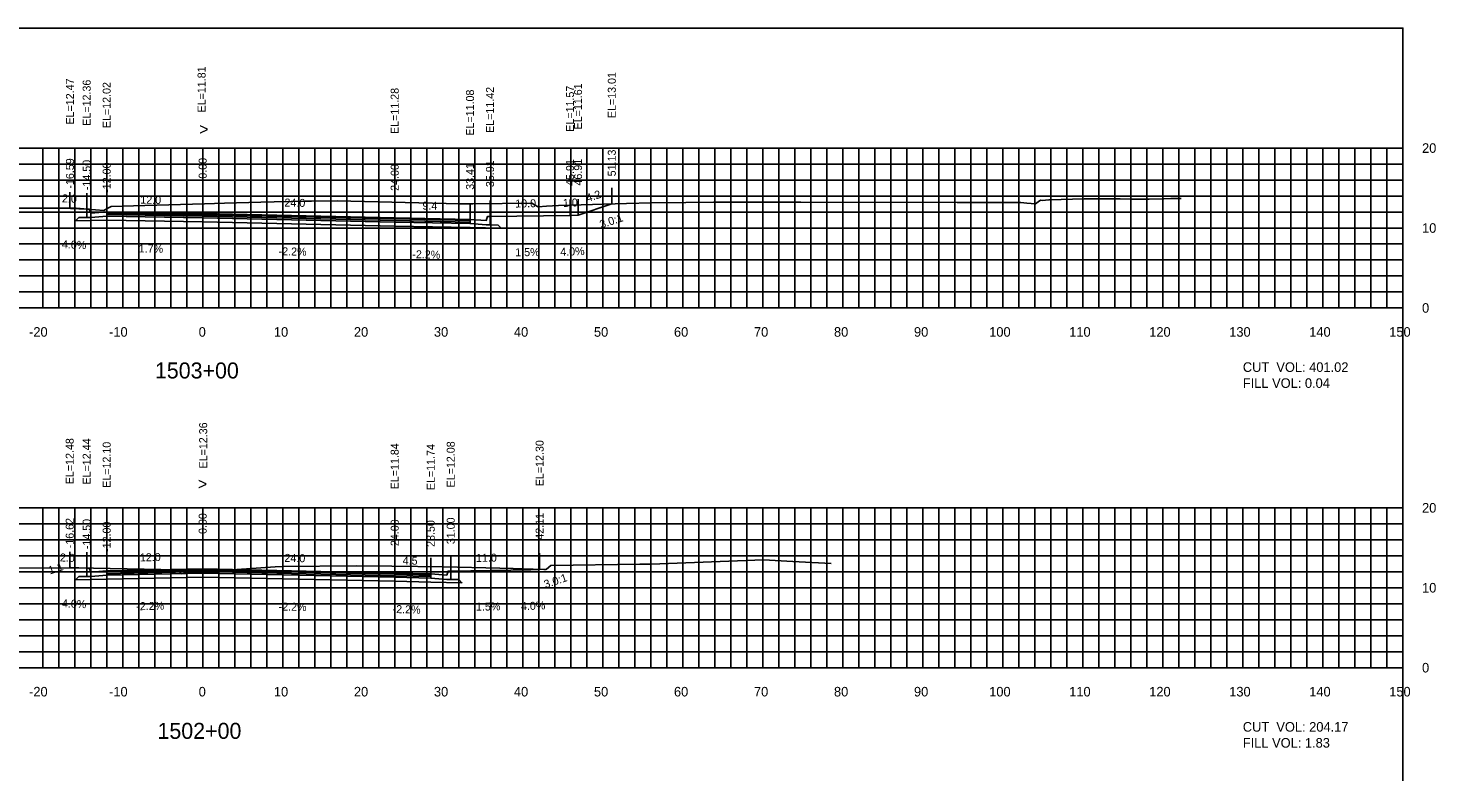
# Model space of a CAD drawing. Extents: x 1800674 to 1802785, y 250079 to 250269.
# Drawn here: x 1802269.2 to 1802445.1, y 250176.4 to 250269.4 of the extents above; entities that cross this region are included whole.
import ezdxf

# ---------------------------------------------------------------- set-up
doc = ezdxf.new("R2010")
doc.units = 0
for name, color, linetype in [('1', 7, 'Continuous'), ('10', 7, 'Continuous'), ('3', 7, 'Continuous'), ('31', 7, 'Continuous'), ('4', 7, 'Continuous'), ('60', 7, 'Continuous'), ('ANNO-TXT', 7, 'Continuous'), ('BASE', 7, 'Continuous'), ('CL-CNST', 7, 'Continuous'), ('Level 62', 7, 'Continuous'), ('LOWER BINDER', 7, 'Continuous'), ('M-ROADS', 7, 'Continuous'), ('UPPER BINDER', 7, 'Continuous'), ('WEARING', 7, 'Continuous')]:
    doc.layers.add(name, color=color, linetype=linetype)

msp = doc.modelspace()

# ---------------------------------------------------------------- linework, layer by layer
for p, q in [((1802342.13, 250247.44), (1802342.13, 250249.44)), ((1802274.41, 250246.9), (1802274.41, 250248.9)), ((1802276.5, 250246.79), (1802276.5, 250248.79)), ((1802279, 250246.45), (1802279, 250248.45)), ((1802291, 250246.24), (1802291, 250248.24)), ((1802315, 250245.71), (1802315, 250247.71)), ((1802324.41, 250245.51), (1802324.41, 250247.51)), ((1802326.91, 250245.85), (1802326.91, 250247.85)), ((1802336.91, 250246), (1802336.91, 250248)), ((1802337.91, 250246.04), (1802337.91, 250248.04)), ((1802274.38, 250201.91), (1802274.38, 250203.91)), ((1802276.5, 250201.87), (1802276.5, 250203.87)), ((1802279, 250201.53), (1802279, 250203.53)), ((1802291, 250201.8), (1802291, 250203.8)), ((1802322, 250201.51), (1802322, 250203.51)), ((1802333.11, 250201.74), (1802333.11, 250203.74)), ((1802315, 250201.27), (1802315, 250203.27)), ((1802319.5, 250201.17), (1802319.5, 250203.17))]:
    msp.add_line(p, q)
for points in [[(1802141, 250079.43), (1802441, 250079.43), (1802441, 250269.43), (1802141, 250269.43)], [(1802279, 250246.45), (1802277, 250246.29), (1802276.83, 250246.79), (1802276.5, 250246.79), (1802276.5, 250245.76), (1802277, 250245.76), (1802279, 250245.92)], [(1802324.41, 250245.51), (1802326.41, 250245.35), (1802326.58, 250245.85), (1802326.91, 250245.85), (1802326.91, 250244.82), (1802326.41, 250244.82), (1802324.41, 250244.98)], [(1802279, 250201.53), (1802277, 250201.37), (1802276.83, 250201.87), (1802276.5, 250201.87), (1802276.5, 250200.84), (1802277, 250200.84), (1802279, 250201)], [(1802319.5, 250201.17), (1802321.5, 250201.01), (1802321.67, 250201.51), (1802322, 250201.51), (1802322, 250200.48), (1802321.5, 250200.48), (1802319.5, 250200.64)]]:
    msp.add_lwpolyline(points, close=True)
msp.add_lwpolyline([(1802274.5, 250201.95), (1802274.38, 250201.91)])
at = {"layer": '60'}
for p, q in [((1802441, 250234.43), (1802441, 250254.43)), ((1802441.06, 250254.43), (1802441, 250254.43)), ((1802441.06, 250244.43), (1802441, 250244.43)), ((1802141, 250234.43), (1802441, 250234.43)), ((1802271, 250234.37), (1802271, 250234.43)), ((1802281, 250234.37), (1802281, 250234.43)), ((1802291, 250234.37), (1802291, 250234.43)), ((1802301, 250234.37), (1802301, 250234.43)), ((1802311, 250234.37), (1802311, 250234.43)), ((1802321, 250234.37), (1802321, 250234.43)), ((1802331, 250234.37), (1802331, 250234.43)), ((1802341, 250234.37), (1802341, 250234.43)), ((1802351, 250234.37), (1802351, 250234.43)), ((1802361, 250234.37), (1802361, 250234.43)), ((1802371, 250234.37), (1802371, 250234.43)), ((1802381, 250234.37), (1802381, 250234.43)), ((1802391, 250234.37), (1802391, 250234.43)), ((1802401, 250234.37), (1802401, 250234.43)), ((1802411, 250234.37), (1802411, 250234.43)), ((1802421, 250234.37), (1802421, 250234.43)), ((1802431, 250234.37), (1802431, 250234.43)), ((1802441, 250234.37), (1802441, 250234.43)), ((1802441.06, 250234.43), (1802441, 250234.43)), ((1802441, 250189.43), (1802441, 250209.43)), ((1802441.06, 250209.43), (1802441, 250209.43)), ((1802441.06, 250199.43), (1802441, 250199.43)), ((1802141, 250189.43), (1802441, 250189.43)), ((1802271, 250189.37), (1802271, 250189.43)), ((1802281, 250189.37), (1802281, 250189.43)), ((1802291, 250189.37), (1802291, 250189.43)), ((1802301, 250189.37), (1802301, 250189.43)), ((1802311, 250189.37), (1802311, 250189.43)), ((1802321, 250189.37), (1802321, 250189.43)), ((1802331, 250189.37), (1802331, 250189.43)), ((1802341, 250189.37), (1802341, 250189.43)), ((1802351, 250189.37), (1802351, 250189.43)), ((1802361, 250189.37), (1802361, 250189.43)), ((1802371, 250189.37), (1802371, 250189.43)), ((1802381, 250189.37), (1802381, 250189.43)), ((1802391, 250189.37), (1802391, 250189.43)), ((1802401, 250189.37), (1802401, 250189.43)), ((1802411, 250189.37), (1802411, 250189.43)), ((1802421, 250189.37), (1802421, 250189.43)), ((1802431, 250189.37), (1802431, 250189.43)), ((1802441, 250189.37), (1802441, 250189.43)), ((1802441.06, 250189.43), (1802441, 250189.43))]:
    msp.add_line(p, q, dxfattribs=at)
at = {"layer": 'BASE'}
for points in [[(1802324.41, 250244.48), (1802328.31, 250244.39), (1802327.91, 250244.8), (1802326.91, 250244.82), (1802326.41, 250244.82), (1802324.41, 250244.98), (1802315, 250245.18), (1802291, 250245.71), (1802279, 250245.92), (1802277, 250245.76), (1802276.5, 250245.76), (1802275.5, 250245.74), (1802275.1, 250245.34), (1802279, 250245.42), (1802291, 250245.21), (1802315, 250244.68)], [(1802319.5, 250200.14), (1802323.4, 250200.05), (1802323, 250200.46), (1802322, 250200.48), (1802321.5, 250200.48), (1802319.5, 250200.64), (1802315, 250200.74), (1802291, 250201.27), (1802279, 250201), (1802277, 250200.84), (1802276.5, 250200.84), (1802275.5, 250200.82), (1802275.1, 250200.42), (1802279, 250200.5), (1802291, 250200.77), (1802315, 250200.24)]]:
    msp.add_lwpolyline(points, close=True, dxfattribs=at)
at = {"layer": 'CL-CNST'}
for points in [[(1802274.41, 250246.9), (1802274.5, 250246.87), (1802276.5, 250246.79), (1802276.83, 250246.79), (1802277, 250246.29), (1802279, 250246.45), (1802291, 250246.24), (1802315, 250245.71), (1802324.41, 250245.51), (1802326.41, 250245.35), (1802326.58, 250245.85), (1802326.91, 250245.85), (1802336.91, 250246), (1802337.91, 250246.04), (1802342.13, 250247.44)], [(1802274.38, 250201.91), (1802274.5, 250201.95), (1802276.5, 250201.87), (1802276.83, 250201.87), (1802277, 250201.37), (1802279, 250201.53), (1802291, 250201.8), (1802315, 250201.27), (1802319.5, 250201.17), (1802321.5, 250201.01), (1802321.67, 250201.51), (1802322, 250201.51), (1802332, 250201.66), (1802333, 250201.7), (1802333.11, 250201.74)]]:
    msp.add_lwpolyline(points, dxfattribs=at)
at = {"layer": 'Level 62'}
for p, q in [((1802141, 250254.43), (1802441, 250254.43)), ((1802271, 250234.43), (1802271, 250254.43)), ((1802273, 250234.43), (1802273, 250254.43)), ((1802275, 250234.43), (1802275, 250254.43)), ((1802277, 250234.43), (1802277, 250254.43)), ((1802279, 250234.43), (1802279, 250254.43)), ((1802281, 250234.43), (1802281, 250254.43)), ((1802283, 250234.43), (1802283, 250254.43)), ((1802285, 250234.43), (1802285, 250254.43)), ((1802287, 250234.43), (1802287, 250254.43)), ((1802289, 250234.43), (1802289, 250254.43)), ((1802291, 250234.43), (1802291, 250254.43)), ((1802293, 250234.43), (1802293, 250254.43)), ((1802295, 250234.43), (1802295, 250254.43)), ((1802297, 250234.43), (1802297, 250254.43)), ((1802299, 250234.43), (1802299, 250254.43)), ((1802301, 250234.43), (1802301, 250254.43)), ((1802303, 250234.43), (1802303, 250254.43)), ((1802305, 250234.43), (1802305, 250254.43)), ((1802307, 250234.43), (1802307, 250254.43)), ((1802309, 250234.43), (1802309, 250254.43)), ((1802311, 250234.43), (1802311, 250254.43)), ((1802313, 250234.43), (1802313, 250254.43)), ((1802315, 250234.43), (1802315, 250254.43)), ((1802317, 250234.43), (1802317, 250254.43)), ((1802319, 250234.43), (1802319, 250254.43)), ((1802321, 250234.43), (1802321, 250254.43)), ((1802323, 250234.43), (1802323, 250254.43)), ((1802325, 250234.43), (1802325, 250254.43)), ((1802327, 250234.43), (1802327, 250254.43)), ((1802329, 250234.43), (1802329, 250254.43)), ((1802331, 250234.43), (1802331, 250254.43)), ((1802333, 250234.43), (1802333, 250254.43)), ((1802335, 250234.43), (1802335, 250254.43)), ((1802337, 250234.43), (1802337, 250254.43)), ((1802339, 250234.43), (1802339, 250254.43)), ((1802341, 250234.43), (1802341, 250254.43)), ((1802343, 250234.43), (1802343, 250254.43)), ((1802345, 250234.43), (1802345, 250254.43)), ((1802347, 250234.43), (1802347, 250254.43)), ((1802349, 250234.43), (1802349, 250254.43)), ((1802351, 250234.43), (1802351, 250254.43)), ((1802353, 250234.43), (1802353, 250254.43)), ((1802355, 250234.43), (1802355, 250254.43)), ((1802357, 250234.43), (1802357, 250254.43)), ((1802359, 250234.43), (1802359, 250254.43)), ((1802361, 250234.43), (1802361, 250254.43)), ((1802363, 250234.43), (1802363, 250254.43)), ((1802365, 250234.43), (1802365, 250254.43)), ((1802367, 250234.43), (1802367, 250254.43)), ((1802369, 250234.43), (1802369, 250254.43)), ((1802371, 250234.43), (1802371, 250254.43)), ((1802373, 250234.43), (1802373, 250254.43)), ((1802375, 250234.43), (1802375, 250254.43)), ((1802377, 250234.43), (1802377, 250254.43)), ((1802379, 250234.43), (1802379, 250254.43)), ((1802381, 250234.43), (1802381, 250254.43)), ((1802383, 250234.43), (1802383, 250254.43)), ((1802385, 250234.43), (1802385, 250254.43)), ((1802387, 250234.43), (1802387, 250254.43)), ((1802389, 250234.43), (1802389, 250254.43)), ((1802391, 250234.43), (1802391, 250254.43)), ((1802393, 250234.43), (1802393, 250254.43)), ((1802395, 250234.43), (1802395, 250254.43)), ((1802397, 250234.43), (1802397, 250254.43)), ((1802399, 250234.43), (1802399, 250254.43)), ((1802401, 250234.43), (1802401, 250254.43)), ((1802403, 250234.43), (1802403, 250254.43)), ((1802405, 250234.43), (1802405, 250254.43)), ((1802407, 250234.43), (1802407, 250254.43)), ((1802409, 250234.43), (1802409, 250254.43)), ((1802411, 250234.43), (1802411, 250254.43)), ((1802413, 250234.43), (1802413, 250254.43)), ((1802415, 250234.43), (1802415, 250254.43)), ((1802417, 250234.43), (1802417, 250254.43)), ((1802419, 250234.43), (1802419, 250254.43)), ((1802421, 250234.43), (1802421, 250254.43)), ((1802423, 250234.43), (1802423, 250254.43)), ((1802425, 250234.43), (1802425, 250254.43)), ((1802427, 250234.43), (1802427, 250254.43)), ((1802429, 250234.43), (1802429, 250254.43)), ((1802431, 250234.43), (1802431, 250254.43)), ((1802433, 250234.43), (1802433, 250254.43)), ((1802435, 250234.43), (1802435, 250254.43)), ((1802437, 250234.43), (1802437, 250254.43)), ((1802439, 250234.43), (1802439, 250254.43)), ((1802441, 250234.43), (1802441, 250254.43)), ((1802141, 250252.43), (1802441, 250252.43)), ((1802141, 250250.43), (1802441, 250250.43)), ((1802141, 250248.43), (1802441, 250248.43)), ((1802141, 250246.43), (1802441, 250246.43)), ((1802141, 250244.43), (1802441, 250244.43)), ((1802141, 250242.43), (1802441, 250242.43)), ((1802141, 250240.43), (1802441, 250240.43)), ((1802141, 250238.43), (1802441, 250238.43)), ((1802141, 250236.43), (1802441, 250236.43)), ((1802141, 250234.43), (1802441, 250234.43)), ((1802141, 250209.43), (1802441, 250209.43)), ((1802271, 250189.43), (1802271, 250209.43)), ((1802273, 250189.43), (1802273, 250209.43)), ((1802275, 250189.43), (1802275, 250209.43)), ((1802277, 250189.43), (1802277, 250209.43)), ((1802279, 250189.43), (1802279, 250209.43)), ((1802281, 250189.43), (1802281, 250209.43)), ((1802283, 250189.43), (1802283, 250209.43)), ((1802285, 250189.43), (1802285, 250209.43)), ((1802287, 250189.43), (1802287, 250209.43)), ((1802289, 250189.43), (1802289, 250209.43)), ((1802291, 250189.43), (1802291, 250209.43)), ((1802293, 250189.43), (1802293, 250209.43)), ((1802295, 250189.43), (1802295, 250209.43)), ((1802297, 250189.43), (1802297, 250209.43)), ((1802299, 250189.43), (1802299, 250209.43)), ((1802301, 250189.43), (1802301, 250209.43)), ((1802303, 250189.43), (1802303, 250209.43)), ((1802305, 250189.43), (1802305, 250209.43)), ((1802307, 250189.43), (1802307, 250209.43)), ((1802309, 250189.43), (1802309, 250209.43)), ((1802311, 250189.43), (1802311, 250209.43)), ((1802313, 250189.43), (1802313, 250209.43)), ((1802315, 250189.43), (1802315, 250209.43)), ((1802317, 250189.43), (1802317, 250209.43)), ((1802319, 250189.43), (1802319, 250209.43)), ((1802321, 250189.43), (1802321, 250209.43)), ((1802323, 250189.43), (1802323, 250209.43)), ((1802325, 250189.43), (1802325, 250209.43)), ((1802327, 250189.43), (1802327, 250209.43)), ((1802329, 250189.43), (1802329, 250209.43)), ((1802331, 250189.43), (1802331, 250209.43)), ((1802333, 250189.43), (1802333, 250209.43)), ((1802335, 250189.43), (1802335, 250209.43)), ((1802337, 250189.43), (1802337, 250209.43)), ((1802339, 250189.43), (1802339, 250209.43)), ((1802341, 250189.43), (1802341, 250209.43)), ((1802343, 250189.43), (1802343, 250209.43)), ((1802345, 250189.43), (1802345, 250209.43)), ((1802347, 250189.43), (1802347, 250209.43)), ((1802349, 250189.43), (1802349, 250209.43)), ((1802351, 250189.43), (1802351, 250209.43)), ((1802353, 250189.43), (1802353, 250209.43)), ((1802355, 250189.43), (1802355, 250209.43)), ((1802357, 250189.43), (1802357, 250209.43)), ((1802359, 250189.43), (1802359, 250209.43)), ((1802361, 250189.43), (1802361, 250209.43)), ((1802363, 250189.43), (1802363, 250209.43)), ((1802365, 250189.43), (1802365, 250209.43)), ((1802367, 250189.43), (1802367, 250209.43)), ((1802369, 250189.43), (1802369, 250209.43)), ((1802371, 250189.43), (1802371, 250209.43)), ((1802373, 250189.43), (1802373, 250209.43)), ((1802375, 250189.43), (1802375, 250209.43)), ((1802377, 250189.43), (1802377, 250209.43)), ((1802379, 250189.43), (1802379, 250209.43)), ((1802381, 250189.43), (1802381, 250209.43)), ((1802383, 250189.43), (1802383, 250209.43)), ((1802385, 250189.43), (1802385, 250209.43)), ((1802387, 250189.43), (1802387, 250209.43)), ((1802389, 250189.43), (1802389, 250209.43)), ((1802391, 250189.43), (1802391, 250209.43)), ((1802393, 250189.43), (1802393, 250209.43)), ((1802395, 250189.43), (1802395, 250209.43)), ((1802397, 250189.43), (1802397, 250209.43)), ((1802399, 250189.43), (1802399, 250209.43)), ((1802401, 250189.43), (1802401, 250209.43)), ((1802403, 250189.43), (1802403, 250209.43)), ((1802405, 250189.43), (1802405, 250209.43)), ((1802407, 250189.43), (1802407, 250209.43)), ((1802409, 250189.43), (1802409, 250209.43)), ((1802411, 250189.43), (1802411, 250209.43)), ((1802413, 250189.43), (1802413, 250209.43)), ((1802415, 250189.43), (1802415, 250209.43)), ((1802417, 250189.43), (1802417, 250209.43)), ((1802419, 250189.43), (1802419, 250209.43)), ((1802421, 250189.43), (1802421, 250209.43)), ((1802423, 250189.43), (1802423, 250209.43)), ((1802425, 250189.43), (1802425, 250209.43)), ((1802427, 250189.43), (1802427, 250209.43)), ((1802429, 250189.43), (1802429, 250209.43)), ((1802431, 250189.43), (1802431, 250209.43)), ((1802433, 250189.43), (1802433, 250209.43)), ((1802435, 250189.43), (1802435, 250209.43)), ((1802437, 250189.43), (1802437, 250209.43)), ((1802439, 250189.43), (1802439, 250209.43)), ((1802441, 250189.43), (1802441, 250209.43)), ((1802141, 250207.43), (1802441, 250207.43)), ((1802141, 250205.43), (1802441, 250205.43)), ((1802141, 250203.43), (1802441, 250203.43)), ((1802141, 250201.43), (1802441, 250201.43)), ((1802141, 250199.43), (1802441, 250199.43)), ((1802141, 250197.43), (1802441, 250197.43)), ((1802141, 250195.43), (1802441, 250195.43)), ((1802141, 250193.43), (1802441, 250193.43)), ((1802141, 250191.43), (1802441, 250191.43)), ((1802141, 250189.43), (1802441, 250189.43))]:
    msp.add_line(p, q, dxfattribs=at)
at = {"layer": 'LOWER BINDER'}
for points in [[(1802279, 250245.92), (1802279, 250246.11), (1802291, 250245.9), (1802315, 250245.37), (1802324.41, 250245.17), (1802324.41, 250244.98), (1802315, 250245.18), (1802291, 250245.71)], [(1802279, 250201), (1802279, 250201.19), (1802291, 250201.46), (1802315, 250200.93), (1802319.5, 250200.83), (1802319.5, 250200.64), (1802315, 250200.74), (1802291, 250201.27)]]:
    msp.add_lwpolyline(points, close=True, dxfattribs=at)
at = {"layer": 'M-ROADS'}
for points in [[(1802265.15, 250246.92), (1802270.89, 250246.9), (1802275.2, 250246.9), (1802275.7, 250246.86), (1802277.59, 250246.71), (1802278.65, 250246.63), (1802279.15, 250246.91), (1802279.56, 250247.12), (1802283.78, 250247.24), (1802291.21, 250247.45), (1802293.73, 250247.52), (1802298.26, 250247.65), (1802299.94, 250247.69), (1802302.04, 250247.74), (1802303.81, 250247.77), (1802304.61, 250247.78), (1802307.8, 250247.81), (1802323.13, 250247.46), (1802324.78, 250247.46), (1802332.13, 250247.55), (1802332.49, 250247.33), (1802332.91, 250247.09), (1802333.96, 250247.15), (1802335.48, 250247.26), (1802343.96, 250247.49), (1802347.09, 250247.57), (1802351.37, 250247.62), (1802354.83, 250247.65), (1802361.94, 250247.66), (1802365.76, 250247.66), (1802385.29, 250247.62), (1802393.24, 250247.63), (1802394.02, 250247.55), (1802395.1, 250247.45), (1802395.41, 250247.71), (1802395.7, 250247.93), (1802395.93, 250247.88), (1802396.77, 250247.97), (1802396.8, 250247.97), (1802396.83, 250247.97), (1802401.19, 250248.07), (1802403.57, 250248.07), (1802405.68, 250248.06), (1802406.96, 250248.05), (1802407.77, 250248.04), (1802409.3, 250248.05), (1802411.13, 250248.09), (1802412.01, 250248.11), (1802413.28, 250248.12)], [(1802255.78, 250201.86), (1802275.21, 250201.91), (1802287.88, 250201.69), (1802287.98, 250201.58), (1802288.32, 250201.19), (1802289.53, 250201.33), (1802289.97, 250201.36), (1802293.47, 250201.59), (1802300.04, 250202.06), (1802300.96, 250202.07), (1802310.27, 250202.19), (1802314.66, 250202.14), (1802321.1, 250202.06), (1802328.14, 250201.88), (1802329.82, 250201.83), (1802332.29, 250201.77), (1802333.64, 250201.71), (1802333.9, 250201.7), (1802333.97, 250201.77), (1802334.51, 250202.23), (1802345.62, 250202.37), (1802346.81, 250202.38), (1802347.07, 250202.39), (1802361.1, 250202.91), (1802364.76, 250202.72), (1802369.56, 250202.48)]]:
    msp.add_lwpolyline(points, dxfattribs=at)
at = {"layer": 'UPPER BINDER'}
for points in [[(1802291, 250245.9), (1802279, 250246.11), (1802279, 250246.3), (1802291, 250246.09), (1802315, 250245.56), (1802324.41, 250245.36), (1802324.41, 250244.98), (1802324.41, 250245.17), (1802315, 250245.37)], [(1802291, 250201.46), (1802279, 250201.19), (1802279, 250201.38), (1802291, 250201.65), (1802315, 250201.12), (1802319.5, 250201.02), (1802319.5, 250200.64), (1802319.5, 250200.83), (1802315, 250200.93)]]:
    msp.add_lwpolyline(points, close=True, dxfattribs=at)
at = {"layer": 'WEARING'}
for points in [[(1802324.41, 250245.36), (1802324.41, 250245.51), (1802315, 250245.71), (1802291, 250246.24), (1802279, 250246.45), (1802279, 250246.3), (1802291, 250246.09), (1802315, 250245.56)], [(1802319.5, 250201.02), (1802319.5, 250201.17), (1802315, 250201.27), (1802291, 250201.8), (1802279, 250201.53), (1802279, 250201.38), (1802291, 250201.65), (1802315, 250201.12)]]:
    msp.add_lwpolyline(points, close=True, dxfattribs=at)

# ---------------------------------------------------------------- texts
for p in [(1802340.81, 250244.37), (1802333.84, 250199.35)]:
    msp.add_text('3.0:1', height=1, rotation=18.4349).set_placement(p)
at = {"layer": '1'}
for s, p in [('1503+00', (1802285.03, 250225.61)), ('1502+00', (1802285.35, 250180.53))]:
    msp.add_text(s, height=2, dxfattribs=at).set_placement(p)
at = {"layer": '10'}
for s, p in [('-20', (1802269.3, 250230.83)), ('-10', (1802279.3, 250230.83)), ('0', (1802290.5, 250230.83)), ('10', (1802299.9, 250230.83)), ('20', (1802309.9, 250230.83)), ('30', (1802319.9, 250230.83)), ('40', (1802329.9, 250230.83)), ('50', (1802339.9, 250230.83)), ('60', (1802349.9, 250230.83)), ('70', (1802359.9, 250230.83)), ('80', (1802369.9, 250230.83)), ('90', (1802379.9, 250230.83)), ('100', (1802389.3, 250230.83)), ('110', (1802399.3, 250230.83)), ('120', (1802409.3, 250230.83)), ('130', (1802419.3, 250230.83)), ('140', (1802429.3, 250230.83)), ('150', (1802439.3, 250230.83)), ('-20', (1802269.3, 250185.83)), ('-10', (1802279.3, 250185.83)), ('0', (1802290.5, 250185.83)), ('10', (1802299.9, 250185.83)), ('20', (1802309.9, 250185.83)), ('30', (1802319.9, 250185.83)), ('40', (1802329.9, 250185.83)), ('50', (1802339.9, 250185.83)), ('60', (1802349.9, 250185.83)), ('70', (1802359.9, 250185.83)), ('80', (1802369.9, 250185.83)), ('90', (1802379.9, 250185.83)), ('100', (1802389.3, 250185.83)), ('110', (1802399.3, 250185.83)), ('120', (1802409.3, 250185.83)), ('130', (1802419.3, 250185.83)), ('140', (1802429.3, 250185.83)), ('150', (1802439.3, 250185.83))]:
    msp.add_text(s, height=1.2, dxfattribs=at).set_placement(p)
at = {"layer": '3'}
for s, p in [('EL=11.81', (1802291.36, 250258.88)), ('EL=13.01', (1802342.63, 250258.17)), ('EL=12.47', (1802274.91, 250257.37)), ('EL=12.36', (1802277, 250257.22)), ('EL=12.02', (1802279.5, 250256.92)), ('EL=11.28', (1802315.5, 250256.19)), ('EL=11.08', (1802324.91, 250255.98)), ('EL=11.42', (1802327.41, 250256.32)), ('EL=11.57', (1802337.41, 250256.47)), ('EL=11.61', (1802338.41, 250256.76)), ('-16.59', (1802274.91, 250249.36)), ('-14.50', (1802277, 250249.17)), ('0.00', (1802291.5, 250250.6)), ('35.91', (1802327.41, 250249.55)), ('45.91', (1802337.41, 250249.7)), ('46.91', (1802338.41, 250249.74)), ('51.13', (1802342.63, 250250.89)), ('-12.00', (1802279.5, 250248.83)), ('24.00', (1802315.5, 250249.08)), ('33.41', (1802324.91, 250249.21)), ('EL=12.36', (1802291.56, 250214.35)), ('EL=12.48', (1802274.88, 250212.38)), ('EL=12.44', (1802277, 250212.34)), ('EL=12.10', (1802279.5, 250211.93)), ('EL=11.84', (1802315.5, 250211.74)), ('EL=12.08', (1802322.5, 250211.98)), ('EL=12.30', (1802333.61, 250212.13)), ('EL=11.74', (1802320, 250211.64)), ('0.00', (1802291.5, 250206.16)), ('42.11', (1802333.61, 250205.44)), ('-16.62', (1802274.88, 250204.37)), ('-14.50', (1802277, 250204.25)), ('-12.00', (1802279.5, 250203.91)), ('24.00', (1802315.5, 250204.64)), ('28.50', (1802320, 250204.54)), ('31.00', (1802322.5, 250204.88))]:
    msp.add_text(s, height=1, rotation=90, dxfattribs=at).set_placement(p)
at = {"layer": '31'}
for s, p in [('20', (1802443.4, 250253.83)), ('10', (1802443.4, 250243.83)), ('0', (1802443.4, 250233.83)), ('20', (1802443.4, 250208.83)), ('10', (1802443.4, 250198.83)), ('0', (1802443.4, 250188.83))]:
    msp.add_text(s, height=1.2, dxfattribs=at).set_placement(p)
at = {"layer": '4'}
for s, rotation, p in [('4.2', 18.4349, (1802339.11, 250247.66)), ('2.0', 357.7094, (1802273.4, 250247.65)), ('12.0', 359.004, (1802283.2, 250247.48)), ('24.0', 358.7397, (1802301.21, 250247.12)), ('9.4', 358.7397, (1802318.45, 250246.74)), ('10.0', 0.8594, (1802330.07, 250246.99)), ('1.0', 2.2906, (1802336.04, 250247.06)), ('4.0%', 357.7094, (1802273.39, 250241.91)), ('1.7%', 359.004, (1802283, 250241.38)), ('-2.2%', 358.7397, (1802300.48, 250241.03)), ('-2.2%', 358.7397, (1802317.19, 250240.66)), ('1.5%', 0.8594, (1802330.07, 250240.89)), ('4.0%', 2.2906, (1802335.7, 250240.94)), ('2.0', 357.7094, (1802273.14, 250202.73)), ('12.0', 1.2603, (1802283.16, 250202.72)), ('24.0', 358.7397, (1802301.21, 250202.67)), ('11.0', 0.8594, (1802325.16, 250202.66)), ('1.1', 18.4349, (1802271.91, 250201.09)), ('4.5', 358.7397, (1802315.99, 250202.35)), ('4.0%', 357.7094, (1802273.39, 250196.99)), ('-2.2%', 1.2603, (1802282.7, 250196.61)), ('-2.2%', 358.7397, (1802300.48, 250196.59)), ('-2.2%', 358.7397, (1802314.73, 250196.27)), ('1.5%', 0.8594, (1802325.16, 250196.56)), ('4.0%', 2.2906, (1802330.79, 250196.61))]:
    msp.add_text(s, height=1, rotation=rotation, dxfattribs=at).set_placement(p)
at = {"layer": '60'}
for p in [(1802290.55, 250256.05), (1802290.39, 250211.68)]:
    msp.add_text('>', height=1.5, dxfattribs=at).set_placement(p)
at = {"layer": 'ANNO-TXT'}
for s, p in [('CUT  VOL: 401.02', (1802421, 250226.43)), ('FILL VOL: 0.04', (1802421, 250224.43)), ('CUT  VOL: 204.17', (1802421, 250181.43)), ('FILL VOL: 1.83', (1802421, 250179.43))]:
    msp.add_text(s, height=1.2, dxfattribs=at).set_placement(p)

doc.saveas('drawing.dxf')
